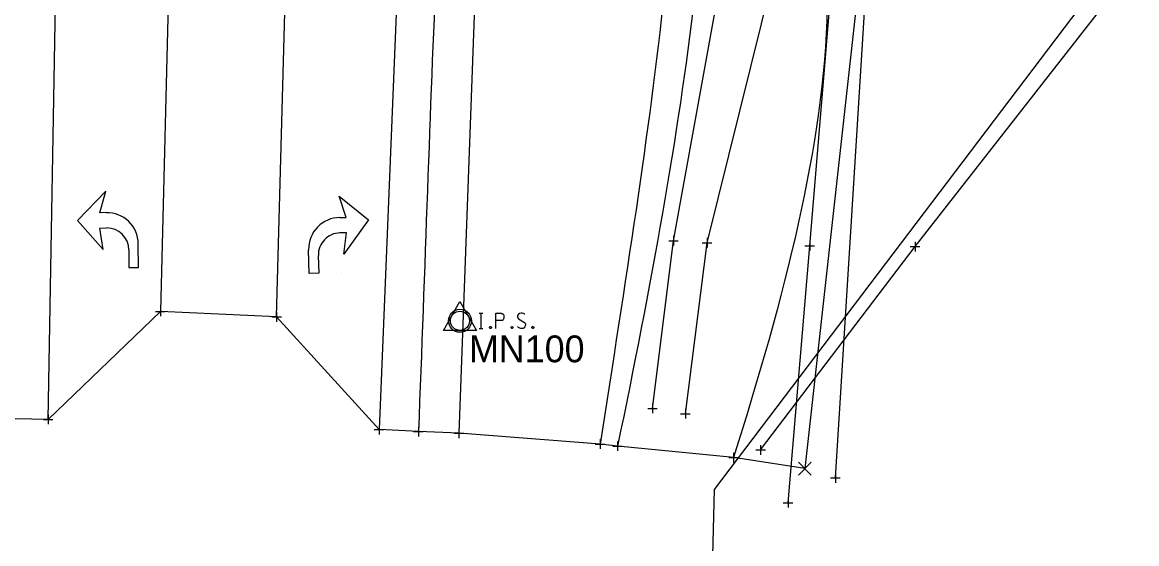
# Model space of a CAD drawing. Extents: x 1391912 to 1392597, y 304167 to 305226.
# Drawn here: x 1392322.5 to 1392438.8, y 304311.7 to 304366.2 of the extents above; entities that cross this region are included whole.
import ezdxf

# ---------------------------------------------------------------- set-up
doc = ezdxf.new("R2010")
doc.units = 0
for name, color, linetype in [('DV_X_Property_Line', 7, 'Continuous'), ('DV_X_Section_VMS_Line', 7, 'Continuous'), ('PM_X_Channelizing_Line', 7, 'Continuous'), ('PM_X_CL_Double_Solid', 7, 'Continuous'), ('PM_X_Edge_Line', 7, 'Continuous'), ('PV_X_EOP', 7, 'Continuous'), ('PV_X_Shoulder_Aggregate', 7, 'Continuous'), ('RW_X_Esmt_SH', 7, 'Continuous'), ('SV_Control_Point', 7, 'Continuous'), ('SV_P_Mon_Cells_Set', 7, 'Continuous'), ('SV_X_Break_Lines', 7, 'Continuous'), ('SV_X_Terrain_Boundary', 7, 'Continuous'), ('SV_X_Text', 7, 'Continuous'), ('SV_X_Toe_of_Slope', 7, 'Continuous'), ('SV_X_Top_of_Bank', 7, 'Continuous'), ('UT_X_FO', 7, 'Continuous'), ('UT_X_Gas', 7, 'Continuous'), ('UT_X_Sanitary_Line', 7, 'Continuous')]:
    doc.layers.add(name, color=color, linetype=linetype)

msp = doc.modelspace()

# ---------------------------------------------------------------- linework, layer by layer
at = {"layer": 'DV_X_Property_Line'}
for p, q in [((1392331.22, 304348.53), (1392328.25, 304345.46)), ((1392330.58, 304346.28), (1392331.22, 304348.53)), ((1392331.22, 304348.53), (1392331.22, 304348.53)), ((1392355.58, 304348.02), (1392355.58, 304348.02)), ((1392356.3, 304345.79), (1392355.58, 304348.02)), ((1392355.58, 304348.02), (1392358.64, 304345.53)), ((1392331.24, 304346.29), (1392330.58, 304346.28)), ((1392355.64, 304345.78), (1392356.3, 304345.79)), ((1392328.25, 304345.46), (1392330.94, 304342.45)), ((1392330.59, 304344.68), (1392331.29, 304344.69)), ((1392330.94, 304342.45), (1392330.59, 304344.68)), ((1392358.64, 304345.53), (1392356.06, 304341.95)), ((1392356.34, 304344.19), (1392355.64, 304344.18)), ((1392356.06, 304341.95), (1392356.34, 304344.19)), ((1392333.61, 304342.41), (1392333.62, 304340.55)), ((1392334.62, 304340.56), (1392334.6, 304343.04)), ((1392352.44, 304339.94), (1392352.38, 304342.42)), ((1392353.39, 304341.83), (1392353.44, 304339.97)), ((1392331.29, 304340.53), (1392331.29, 304340.53)), ((1392333.62, 304340.55), (1392334.62, 304340.56)), ((1392353.44, 304339.97), (1392352.44, 304339.94)), ((1392355.77, 304340.02), (1392355.77, 304340.02))]:
    msp.add_line(p, q, dxfattribs=at)
for centre, radius, start, end in [((1392331.32, 304343.01), 3.28, 0.4837, 91.3922), ((1392355.66, 304342.5), 3.28, 90.4116, 181.3201), ((1392331.31, 304342.39), 2.3, 0.4837, 90.4837), ((1392355.69, 304341.88), 2.3, 91.3201, 181.3201)]:
    msp.add_arc(centre, radius, start, end, dxfattribs=at)
at = {"layer": 'DV_X_Section_VMS_Line'}
for p, q in [((1392403.51, 304318.9), (1392404.84, 304320.24)), ((1392403.51, 304320.24), (1392404.84, 304318.9))]:
    msp.add_line(p, q, dxfattribs=at)
at = {"layer": 'PM_X_Channelizing_Line'}
for points in [[(1392339.19, 304434.91), (1392338.84, 304422.93), (1392337.86, 304373.67), (1392336.91, 304335.98)], [(1392349.04, 304335.4), (1392350.06, 304373.54), (1392351.03, 304423.84), (1392351.23, 304434.34)]]:
    msp.add_lwpolyline(points, dxfattribs=at)
at = {"layer": 'PM_X_CL_Double_Solid'}
msp.add_lwpolyline([(1392325.19, 304324.71), (1392326.06, 304374), (1392327, 304423.76), (1392327.25, 304435.44)], dxfattribs=at)
at = {"layer": 'PM_X_Edge_Line'}
msp.add_line((1392361.8, 304374.11), (1392359.73, 304323.64), dxfattribs=at)
at = {"layer": 'PV_X_EOP'}
msp.add_open_spline([(1392378.24, 304452.75), (1392374.59, 304449.68), (1392367.73, 304441.64), (1392368.05, 304412.94), (1392365.56, 304374.27), (1392364.51, 304340.35), (1392363.84, 304323.44)], degree=3, dxfattribs=at)
at = {"layer": 'PV_X_Shoulder_Aggregate'}
msp.add_line((1392369.9, 304373.3), (1392368.06, 304323.26), dxfattribs=at)
at = {"layer": 'RW_X_Esmt_SH'}
for p, q in [((1392389.96, 304343.36), (1392390.96, 304343.36)), ((1392390.46, 304343.86), (1392390.46, 304342.86)), ((1392390.46, 304343.36), (1392390.46, 304343.36)), ((1392393.97, 304343.65), (1392393.97, 304342.65)), ((1392393.47, 304343.15), (1392394.47, 304343.15)), ((1392393.97, 304343.15), (1392393.97, 304343.15)), ((1392404.18, 304342.84), (1392405.18, 304342.84)), ((1392404.68, 304343.34), (1392404.68, 304342.34)), ((1392404.68, 304342.84), (1392404.68, 304342.84)), ((1392415.17, 304342.75), (1392416.17, 304342.75)), ((1392415.67, 304343.25), (1392415.67, 304342.25)), ((1392415.67, 304342.75), (1392415.67, 304342.75)), ((1392336.91, 304336.48), (1392336.91, 304335.48)), ((1392336.41, 304335.98), (1392337.41, 304335.98)), ((1392336.91, 304335.98), (1392336.91, 304335.98)), ((1392348.54, 304335.4), (1392349.54, 304335.4)), ((1392349.04, 304335.9), (1392349.04, 304334.9)), ((1392349.04, 304335.4), (1392349.04, 304335.4)), ((1392388.27, 304326.35), (1392388.27, 304325.35)), ((1392325.19, 304325.21), (1392325.19, 304324.21)), ((1392387.77, 304325.85), (1392388.77, 304325.85)), ((1392388.27, 304325.85), (1392388.27, 304325.85)), ((1392391.2, 304325.3), (1392392.2, 304325.3)), ((1392391.7, 304325.8), (1392391.7, 304324.8)), ((1392391.7, 304325.3), (1392391.7, 304325.3)), ((1392324.69, 304324.71), (1392325.69, 304324.71)), ((1392325.19, 304324.71), (1392325.19, 304324.71)), ((1392359.23, 304323.64), (1392360.23, 304323.64)), ((1392359.73, 304324.14), (1392359.73, 304323.14)), ((1392359.73, 304323.64), (1392359.73, 304323.64)), ((1392363.84, 304323.94), (1392363.84, 304322.94)), ((1392368.06, 304323.76), (1392368.06, 304322.76)), ((1392363.34, 304323.44), (1392364.34, 304323.44)), ((1392363.84, 304323.44), (1392363.84, 304323.44)), ((1392367.56, 304323.26), (1392368.56, 304323.26)), ((1392368.06, 304323.26), (1392368.06, 304323.26)), ((1392382.8, 304322.64), (1392382.8, 304321.64)), ((1392384.62, 304322.42), (1392384.62, 304321.42)), ((1392382.3, 304322.14), (1392383.3, 304322.14)), ((1392382.8, 304322.14), (1392382.8, 304322.14)), ((1392384.12, 304321.92), (1392385.12, 304321.92)), ((1392384.62, 304321.92), (1392384.62, 304321.92)), ((1392399.05, 304321.52), (1392400.05, 304321.52)), ((1392399.55, 304322.02), (1392399.55, 304321.02)), ((1392399.55, 304321.52), (1392399.55, 304321.52)), ((1392396.22, 304320.72), (1392397.22, 304320.72)), ((1392396.72, 304321.22), (1392396.72, 304320.22)), ((1392396.72, 304320.72), (1392396.72, 304320.72)), ((1392407.36, 304319.1), (1392407.36, 304318.1)), ((1392406.86, 304318.6), (1392407.86, 304318.6)), ((1392407.36, 304318.6), (1392407.36, 304318.6)), ((1392401.92, 304316.01), (1392402.92, 304316.01)), ((1392402.42, 304316.51), (1392402.42, 304315.51)), ((1392402.42, 304316.01), (1392402.42, 304316.01))]:
    msp.add_line(p, q, dxfattribs=at)
at = {"layer": 'SV_Control_Point'}
msp.add_line((1392368.17, 304335), (1392368.17, 304335), dxfattribs=at)
msp.add_lwpolyline([(1392366.44, 304334), (1392368.17, 304337), (1392369.91, 304334)], close=True, dxfattribs=at)
msp.add_circle((1392368.17, 304335), 1, dxfattribs=at)
at = {"layer": 'SV_P_Mon_Cells_Set'}
for points in [[(1392370.19, 304335.8), (1392370.55, 304335.8)], [(1392370.37, 304334.2), (1392370.37, 304335.8)], [(1392371.93, 304334.2), (1392371.93, 304335.8), (1392372.46, 304335.8), (1392372.52, 304335.78), (1392372.6, 304335.76), (1392372.63, 304335.73), (1392372.66, 304335.71), (1392372.71, 304335.65), (1392372.74, 304335.58), (1392372.76, 304335.48), (1392372.76, 304335.33), (1392372.75, 304335.28), (1392372.73, 304335.21), (1392372.68, 304335.12), (1392372.64, 304335.08), (1392372.61, 304335.05), (1392372.55, 304335.03), (1392372.46, 304335.02), (1392371.93, 304335.02)], [(1392374.94, 304335.68), (1392374.92, 304335.71), (1392374.89, 304335.73), (1392374.79, 304335.77), (1392374.67, 304335.8), (1392374.58, 304335.8), (1392374.55, 304335.8), (1392374.4, 304335.76), (1392374.28, 304335.68), (1392374.21, 304335.58), (1392374.18, 304335.48), (1392374.18, 304335.41), (1392374.21, 304335.31), (1392374.29, 304335.22), (1392374.9, 304334.84), (1392374.95, 304334.79), (1392374.98, 304334.74), (1392375, 304334.66), (1392375, 304334.59), (1392374.99, 304334.51), (1392374.98, 304334.46), (1392374.95, 304334.4), (1392374.93, 304334.35), (1392374.91, 304334.31), (1392374.88, 304334.27), (1392374.84, 304334.25), (1392374.8, 304334.22), (1392374.77, 304334.21), (1392374.67, 304334.2), (1392374.51, 304334.2), (1392374.41, 304334.22), (1392374.27, 304334.31), (1392374.18, 304334.39)], [(1392370.19, 304334.2), (1392370.55, 304334.2)], [(1392371.33, 304334.41), (1392371.38, 304334.41), (1392371.42, 304334.39), (1392371.45, 304334.34), (1392371.45, 304334.27), (1392371.42, 304334.22), (1392371.38, 304334.2), (1392371.33, 304334.2), (1392371.3, 304334.22), (1392371.26, 304334.27), (1392371.26, 304334.34), (1392371.3, 304334.39), (1392371.33, 304334.41)], [(1392373.58, 304334.41), (1392373.63, 304334.41), (1392373.67, 304334.39), (1392373.7, 304334.34), (1392373.7, 304334.27), (1392373.67, 304334.22), (1392373.63, 304334.2), (1392373.58, 304334.2), (1392373.54, 304334.22), (1392373.51, 304334.27), (1392373.51, 304334.34), (1392373.54, 304334.39), (1392373.58, 304334.41)], [(1392375.76, 304334.41), (1392375.81, 304334.41), (1392375.85, 304334.39), (1392375.88, 304334.34), (1392375.88, 304334.27), (1392375.85, 304334.22), (1392375.81, 304334.2), (1392375.76, 304334.2), (1392375.73, 304334.22), (1392375.69, 304334.27), (1392375.69, 304334.34), (1392375.73, 304334.39), (1392375.76, 304334.41)]]:
    msp.add_lwpolyline(points, dxfattribs=at)
msp.add_circle((1392368.17, 304335), 1.2, dxfattribs=at)
at = {"layer": 'SV_X_Break_Lines'}
msp.add_open_spline([(1392439.02, 304468.35), (1392430.22, 304466.36), (1392417.03, 304460.14), (1392402.39, 304445.83), (1392398.08, 304431.17), (1392394.86, 304407.24), (1392393.94, 304370.59), (1392388.07, 304338.52), (1392384.62, 304321.92)], degree=3, dxfattribs=at)
at = {"layer": 'SV_X_Terrain_Boundary'}
msp.add_lwpolyline([(1392444.41, 304447.07), (1392426.36, 304441.44), (1392414.71, 304421.65), (1392409.91, 304371.29), (1392404.17, 304319.57), (1392396.72, 304320.72), (1392384.62, 304321.92), (1392382.8, 304322.14), (1392368.06, 304323.26), (1392363.84, 304323.44), (1392359.73, 304323.64), (1392349.04, 304335.4), (1392336.91, 304335.98), (1392325.19, 304324.71), (1392313.17, 304324.96)], dxfattribs=at)
at = {"layer": 'SV_X_Toe_of_Slope'}
msp.add_open_spline([(1392438.7, 304469.65), (1392429.7, 304467.69), (1392416.24, 304461.41), (1392400.71, 304446.97), (1392396.8, 304431.68), (1392391.77, 304407.83), (1392390.55, 304371.01), (1392385.4, 304338.88), (1392382.8, 304322.14)], degree=3, dxfattribs=at)
at = {"layer": 'SV_X_Top_of_Bank'}
msp.add_open_spline([(1392421.16, 304450.78), (1392415.89, 304448.41), (1392409.07, 304441.73), (1392404.42, 304429.29), (1392399.45, 304406.29), (1392410.44, 304369.54), (1392401.99, 304337.41), (1392396.72, 304320.72)], degree=3, dxfattribs=at)
at = {"layer": 'UT_X_FO'}
for points in [[(1392388.27, 304325.85), (1392390.46, 304343.36), (1392397.86, 304384.26), (1392415.44, 304444.05)], [(1392391.7, 304325.3), (1392393.97, 304343.15), (1392404.21, 304384.41), (1392417.91, 304441.96)], [(1392402.42, 304316.01), (1392404.68, 304342.84), (1392408.12, 304384.25), (1392420.02, 304442.08)], [(1392407.36, 304318.6), (1392411.45, 304384.03), (1392422.06, 304440.89)]]:
    msp.add_lwpolyline(points, dxfattribs=at)
at = {"layer": 'UT_X_Gas'}
msp.add_lwpolyline([(1392399.55, 304321.52), (1392415.67, 304342.75), (1392435.46, 304368.01), (1392455.37, 304392.91), (1392476.59, 304421.48), (1392493.88, 304443.91)], dxfattribs=at)
at = {"layer": 'UT_X_Sanitary_Line'}
for p, q in [((1392394.73, 304317.39), (1392509.85, 304469.25)), ((1392390.87, 304167.39), (1392394.73, 304317.39))]:
    msp.add_line(p, q, dxfattribs=at)

# ---------------------------------------------------------------- texts
at = {"layer": 'SV_X_Text'}
msp.add_text('MN100', height=2.8, dxfattribs=at).set_placement((1392369.11, 304330.67))

doc.saveas('drawing.dxf')
